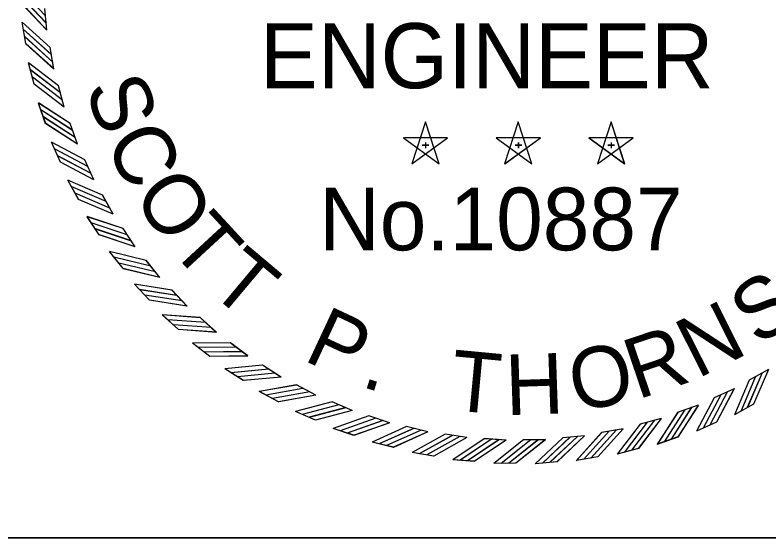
# Model space of a CAD drawing. Extents: x 0 to 1228740, y 0 to 152440.
# Drawn here: x 30.834 to 32.648, y 17.405 to 18.662 of the extents above; entities that cross this region are included whole.
import ezdxf

# ---------------------------------------------------------------- set-up
doc = ezdxf.new("R2010")
doc.units = 0
for name, color, linetype in [('R_No Plot', 7, 'Continuous'), ('R_Sheet Text', 7, 'Continuous'), ('STAMP', 7, 'Continuous')]:
    doc.layers.add(name, color=color, linetype=linetype)

msp = doc.modelspace()

# ---------------------------------------------------------------- linework, layer by layer
at = {"layer": 'R_No Plot'}
msp.add_lwpolyline([(30.6665, 20.1618), (33.4231, 20.1618), (33.4231, 17.4052), (30.6665, 17.4052)], close=True, dxfattribs=at)
msp.add_lwpolyline([(30.6665, 20.1432), (30.6665, 17.4052), (33.4231, 17.4052)], dxfattribs=at)
msp.add_lwpolyline([(30.6665, 20.1432), (30.6665, 17.4052), (33.4231, 17.4052)], dxfattribs=at)
at = {"layer": 'R_Sheet Text'}
for p, q in [((30.9105, 18.6254), (30.9057, 18.6779)), ((30.8599, 18.5933), (30.8508, 18.6451)), ((30.9275, 18.5323), (30.9184, 18.5842)), ((30.8798, 18.4961), (30.8664, 18.547)), ((30.9522, 18.4409), (30.9388, 18.4919)), ((30.9076, 18.4009), (30.89, 18.4505)), ((30.9843, 18.3519), (30.9667, 18.4016)), ((31.8214, 18.4051), (31.7885, 18.3041)), ((31.8542, 18.3042), (31.8215, 18.4053)), ((32.0446, 18.4051), (32.0117, 18.3041)), ((32.0774, 18.3042), (32.0447, 18.4053)), ((32.2678, 18.4051), (32.2349, 18.3041)), ((32.3006, 18.3042), (32.2679, 18.4053)), ((30.9432, 18.3083), (30.9216, 18.3563)), ((31.8745, 18.3666), (31.7682, 18.3667)), ((31.7683, 18.3666), (31.8542, 18.3041)), ((31.7886, 18.3042), (31.8746, 18.3666)), ((31.8215, 18.3553), (31.8215, 18.342)), ((32.0977, 18.3666), (31.9914, 18.3667)), ((31.9915, 18.3666), (32.0774, 18.3041)), ((32.0118, 18.3042), (32.0978, 18.3666)), ((32.0447, 18.3553), (32.0447, 18.342)), ((32.3209, 18.3666), (32.2147, 18.3667)), ((32.2147, 18.3666), (32.3006, 18.3041)), ((32.235, 18.3042), (32.321, 18.3666)), ((32.2679, 18.3553), (32.2679, 18.342)), ((31.8138, 18.3496), (31.8296, 18.3496)), ((32.037, 18.3496), (32.0528, 18.3496)), ((32.2603, 18.3496), (32.276, 18.3496)), ((31.0237, 18.2658), (31.0021, 18.3139)), ((30.9863, 18.219), (30.9608, 18.265)), ((31.07, 18.1832), (31.0445, 18.2294)), ((31.0366, 18.1335), (31.0074, 18.1773)), ((31.1231, 18.1048), (31.0938, 18.1487)), ((31.0939, 18.0525), (31.0612, 18.0937)), ((31.1824, 18.031), (31.1496, 18.0723)), ((31.1576, 17.9764), (31.1216, 18.0148)), ((31.2475, 17.9624), (31.2115, 18.0008)), ((31.2274, 17.9059), (31.1883, 17.9412)), ((31.3182, 17.8993), (31.279, 17.9347)), ((31.3027, 17.8415), (31.2609, 17.8734)), ((31.3938, 17.8424), (31.3519, 17.8744)), ((31.3832, 17.7834), (31.3388, 17.8118)), ((31.4738, 17.7918), (31.4294, 17.8203)), ((32.6463, 17.8101), (32.6001, 17.7846)), ((31.4681, 17.7322), (31.4216, 17.7568)), ((31.5578, 17.7481), (31.5112, 17.7728)), ((32.5637, 17.7638), (32.5156, 17.7421)), ((31.645, 17.7114), (31.5966, 17.7322)), ((32.4776, 17.7244), (32.4279, 17.7068)), ((32.6105, 17.7264), (32.5645, 17.7009)), ((31.557, 17.6882), (31.5086, 17.7089)), ((31.7351, 17.6821), (31.685, 17.6987)), ((32.3886, 17.6923), (32.3376, 17.6789)), ((31.6492, 17.6516), (31.5993, 17.6683)), ((31.8272, 17.6603), (31.7759, 17.6728)), ((32.2972, 17.6676), (32.2453, 17.6584)), ((32.5212, 17.6833), (32.4732, 17.6617)), ((31.9208, 17.6462), (31.8687, 17.6544)), ((32.2041, 17.6506), (32.1516, 17.6457)), ((32.4286, 17.6477), (32.379, 17.6301)), ((31.7442, 17.6229), (31.693, 17.6353)), ((32.0152, 17.6398), (31.9626, 17.6437)), ((32.1099, 17.6413), (32.0571, 17.6408)), ((32.3334, 17.6198), (32.2825, 17.6065)), ((31.8411, 17.602), (31.7891, 17.6102)), ((31.9395, 17.5892), (31.887, 17.5931)), ((32.2362, 17.6), (32.1844, 17.5909)), ((32.0386, 17.5846), (31.986, 17.5841)), ((32.1377, 17.5882), (32.0853, 17.5834))]:
    msp.add_line(p, q, dxfattribs=at)
for points in [[(30.9071, 18.6604), (30.8447, 18.7268)], [(30.9091, 18.6422), (30.8468, 18.7086)], [(30.9105, 18.6254), (30.8482, 18.6917)], [(30.9183, 18.5842), (30.8507, 18.6452)], [(30.9212, 18.5669), (30.8536, 18.6279)], [(30.9248, 18.5489), (30.8572, 18.6099)], [(30.9276, 18.5322), (30.86, 18.5932)], [(30.9388, 18.4918), (30.8663, 18.547)], [(30.9431, 18.4748), (30.8706, 18.53)], [(30.9481, 18.4573), (30.8757, 18.5125)], [(30.9523, 18.4409), (30.8798, 18.496)], [(30.9667, 18.4015), (30.89, 18.4505)], [(30.9724, 18.3849), (30.8957, 18.434)], [(30.9789, 18.3678), (30.9022, 18.4169)], [(30.9844, 18.3518), (30.9077, 18.4008)], [(31.0021, 18.3138), (30.9215, 18.3563)], [(31.0091, 18.2977), (30.9286, 18.3403)], [(31.017, 18.2812), (30.9364, 18.3238)], [(31.0238, 18.2657), (30.9433, 18.3082)], [(31.0445, 18.2293), (30.9608, 18.265)], [(31.0529, 18.2139), (30.9691, 18.2496)], [(31.0621, 18.1981), (30.9783, 18.2338)], [(31.0701, 18.1832), (30.9864, 18.2189)], [(31.0938, 18.1486), (31.0074, 18.1773)], [(31.1034, 18.1339), (31.017, 18.1626)], [(31.1139, 18.1189), (31.0274, 18.1476)], [(31.1231, 18.1048), (31.0367, 18.1335)], [(31.1496, 18.0723), (31.0611, 18.0937)], [(31.1604, 18.0584), (31.0719, 18.0799)], [(31.172, 18.0444), (31.0835, 18.0658)], [(31.1824, 18.031), (31.0939, 18.0524)], [(31.2115, 18.0008), (31.1215, 18.0148)], [(31.2234, 17.9879), (31.1334, 18.0019)], [(31.2362, 17.9748), (31.1462, 17.9889)], [(31.2476, 17.9624), (31.1577, 17.9764)], [(31.2791, 17.9346), (31.1883, 17.9412)], [(31.292, 17.9228), (31.2012, 17.9294)], [(31.3058, 17.9108), (31.215, 17.9174)], [(31.3183, 17.8993), (31.2274, 17.9059)], [(31.3519, 17.8743), (31.2608, 17.8734)], [(31.3657, 17.8636), (31.2747, 17.8626)], [(31.3805, 17.8528), (31.2894, 17.8519)], [(31.3939, 17.8424), (31.3028, 17.8414)], [(31.4294, 17.8202), (31.3388, 17.8118)], [(31.4441, 17.8106), (31.3535, 17.8022)], [(31.4597, 17.8011), (31.3691, 17.7927)], [(32.6156, 17.7929), (32.5799, 17.7092)], [(32.6314, 17.8021), (32.5957, 17.7184)], [(32.6463, 17.8102), (32.6106, 17.7264)], [(31.4739, 17.7918), (31.3832, 17.7834)], [(32.6002, 17.7846), (32.5645, 17.7008)], [(31.5112, 17.7727), (31.4215, 17.7568)], [(31.5266, 17.7644), (31.437, 17.7485)], [(31.543, 17.7562), (31.4533, 17.7403)], [(32.5483, 17.757), (32.5057, 17.6765)], [(32.5638, 17.7638), (32.5212, 17.6833)], [(31.5579, 17.7481), (31.4682, 17.7322)], [(32.5157, 17.7421), (32.4732, 17.6616)], [(32.5318, 17.7492), (32.4892, 17.6687)], [(31.5966, 17.7321), (31.5086, 17.7089)], [(31.6127, 17.7251), (31.5246, 17.7018)], [(32.4777, 17.7245), (32.4287, 17.6477)], [(31.6296, 17.7182), (31.5416, 17.695)], [(31.6451, 17.7114), (31.5571, 17.6882)], [(32.428, 17.7068), (32.379, 17.6301)], [(32.4446, 17.7125), (32.3955, 17.6358)], [(32.4617, 17.719), (32.4126, 17.6422)], [(31.6851, 17.6987), (31.5992, 17.6683)], [(31.7016, 17.693), (31.6158, 17.6626)], [(31.7191, 17.6876), (31.6333, 17.6572)], [(32.3722, 17.6882), (32.317, 17.6158)], [(32.3886, 17.6923), (32.3335, 17.6199)], [(31.7351, 17.6821), (31.6493, 17.6517)], [(31.776, 17.6727), (31.693, 17.6353)], [(31.793, 17.6684), (31.71, 17.631)], [(32.2973, 17.6677), (32.2363, 17.6001)], [(32.3377, 17.6788), (32.2825, 17.6064)], [(32.3547, 17.6831), (32.2995, 17.6107)], [(31.8108, 17.6645), (31.7278, 17.627)], [(31.8272, 17.6603), (31.7442, 17.6229)], [(31.8687, 17.6543), (31.7891, 17.6102)], [(31.886, 17.6514), (31.8064, 17.6073)], [(31.9041, 17.649), (31.8245, 17.6048)], [(32.1691, 17.6471), (32.1027, 17.5848)], [(32.1873, 17.6492), (32.1209, 17.5869)], [(32.2041, 17.6506), (32.1378, 17.5883)], [(32.2453, 17.6584), (32.1843, 17.5908)], [(32.2626, 17.6613), (32.2016, 17.5937)], [(32.2806, 17.6649), (32.2196, 17.5973)], [(31.9208, 17.6462), (31.8412, 17.602)], [(31.9627, 17.6436), (31.887, 17.5931)], [(31.9802, 17.6422), (31.9044, 17.5916)], [(31.9984, 17.6413), (31.9227, 17.5907)], [(32.0153, 17.6399), (31.9396, 17.5893)], [(32.0572, 17.6408), (31.9859, 17.5841)], [(32.0747, 17.6408), (32.0034, 17.5841)], [(32.093, 17.6413), (32.0217, 17.5847)], [(32.1099, 17.6413), (32.0387, 17.5847)], [(32.1516, 17.6457), (32.0853, 17.5834)]]:
    msp.add_lwpolyline(points, dxfattribs=at)
at = {"layer": 'STAMP'}
for p, q in [((30.9106, 18.6256), (30.9058, 18.6781)), ((30.86, 18.5934), (30.8509, 18.6453)), ((30.9276, 18.5324), (30.9185, 18.5844)), ((30.8799, 18.4962), (30.8665, 18.5471)), ((30.9523, 18.441), (30.9389, 18.492)), ((30.9077, 18.401), (30.8902, 18.4506)), ((30.9844, 18.352), (30.9669, 18.4017)), ((31.8215, 18.4053), (31.7886, 18.3043)), ((31.8543, 18.3043), (31.8216, 18.4054)), ((32.0448, 18.4053), (32.0118, 18.3043)), ((32.0776, 18.3043), (32.0448, 18.4054)), ((32.268, 18.4053), (32.2351, 18.3043)), ((32.3008, 18.3043), (32.2681, 18.4054)), ((30.9433, 18.3084), (30.9217, 18.3564)), ((31.8746, 18.3667), (31.7684, 18.3668)), ((31.7685, 18.3667), (31.8544, 18.3042)), ((31.7887, 18.3043), (31.8748, 18.3667)), ((31.8216, 18.3554), (31.8216, 18.3421)), ((32.0978, 18.3667), (31.9916, 18.3668)), ((31.9917, 18.3667), (32.0776, 18.3042)), ((32.012, 18.3043), (32.098, 18.3667)), ((32.0449, 18.3554), (32.0449, 18.3421)), ((32.3211, 18.3667), (32.2148, 18.3668)), ((32.2149, 18.3667), (32.3008, 18.3042)), ((32.2352, 18.3043), (32.3212, 18.3667)), ((32.2681, 18.3554), (32.2681, 18.3421)), ((31.814, 18.3497), (31.8298, 18.3497)), ((32.0372, 18.3497), (32.053, 18.3497)), ((32.2604, 18.3497), (32.2762, 18.3497)), ((31.0238, 18.2659), (31.0022, 18.314)), ((30.9864, 18.2191), (30.9609, 18.2651)), ((31.0702, 18.1834), (31.0446, 18.2295)), ((31.0367, 18.1336), (31.0076, 18.1774)), ((31.1232, 18.1049), (31.0939, 18.1488)), ((31.094, 18.0526), (31.0613, 18.0938)), ((31.1825, 18.0311), (31.1497, 18.0725)), ((31.1577, 17.9766), (31.1217, 18.015)), ((31.2477, 17.9625), (31.2116, 18.001)), ((31.2275, 17.9061), (31.1884, 17.9413)), ((31.3183, 17.8995), (31.2792, 17.9348)), ((31.3029, 17.8416), (31.261, 17.8735)), ((31.3939, 17.8425), (31.352, 17.8745)), ((31.3833, 17.7835), (31.339, 17.8119)), ((31.474, 17.792), (31.4295, 17.8204)), ((32.6465, 17.8102), (32.6003, 17.7847)), ((31.4682, 17.7323), (31.4217, 17.7569)), ((31.5579, 17.7482), (31.5113, 17.7729)), ((32.5639, 17.7639), (32.5158, 17.7423)), ((31.6452, 17.7115), (31.5967, 17.7323)), ((32.4778, 17.7245), (32.4281, 17.7069)), ((32.6107, 17.7265), (32.5647, 17.701)), ((31.5571, 17.6883), (31.5088, 17.709)), ((31.7352, 17.6822), (31.6852, 17.6989)), ((32.3888, 17.6924), (32.3378, 17.679)), ((32.5214, 17.6834), (32.4734, 17.6618)), ((31.6494, 17.6518), (31.5994, 17.6684)), ((31.8273, 17.6604), (31.7761, 17.6729)), ((32.2974, 17.6677), (32.2454, 17.6586)), ((31.9209, 17.6463), (31.8688, 17.6545)), ((32.2042, 17.6507), (32.1517, 17.6458)), ((32.4288, 17.6478), (32.3792, 17.6302)), ((31.7443, 17.623), (31.6932, 17.6354)), ((32.0154, 17.6399), (31.9628, 17.6438)), ((32.11, 17.6414), (32.0573, 17.6409)), ((32.3336, 17.62), (32.2827, 17.6066)), ((31.8413, 17.6021), (31.7893, 17.6103)), ((31.9397, 17.5893), (31.8872, 17.5932)), ((32.2364, 17.6001), (32.1845, 17.591)), ((32.0387, 17.5847), (31.9861, 17.5842)), ((32.1379, 17.5883), (32.0855, 17.5835))]:
    msp.add_line(p, q, dxfattribs=at)
for points in [[(30.9072, 18.6605), (30.8448, 18.7269)], [(30.9093, 18.6424), (30.8469, 18.7087)], [(30.9107, 18.6255), (30.8483, 18.6919)], [(30.9185, 18.5843), (30.8508, 18.6453)], [(30.9213, 18.567), (30.8537, 18.628)], [(30.9249, 18.5491), (30.8573, 18.6101)], [(30.9277, 18.5324), (30.8601, 18.5934)], [(30.9389, 18.492), (30.8664, 18.5472)], [(30.9432, 18.475), (30.8708, 18.5302)], [(30.9482, 18.4574), (30.8758, 18.5126)], [(30.9524, 18.441), (30.8799, 18.4962)], [(30.9668, 18.4016), (30.8901, 18.4507)], [(30.9725, 18.3851), (30.8958, 18.4341)], [(30.979, 18.368), (30.9023, 18.417)], [(30.9845, 18.3519), (30.9078, 18.401)], [(31.0022, 18.3139), (30.9217, 18.3565)], [(31.0092, 18.2979), (30.9287, 18.3404)], [(31.0171, 18.2814), (30.9366, 18.3239)], [(31.0239, 18.2659), (30.9434, 18.3084)], [(31.0446, 18.2294), (30.9609, 18.2652)], [(31.053, 18.214), (30.9692, 18.2497)], [(31.0622, 18.1982), (30.9784, 18.2339)], [(31.0702, 18.1833), (30.9865, 18.219)], [(31.0939, 18.1487), (31.0075, 18.1774)], [(31.1035, 18.1341), (31.0171, 18.1627)], [(31.114, 18.1191), (31.0276, 18.1478)], [(31.1232, 18.1049), (31.0368, 18.1336)], [(31.1497, 18.0724), (31.0612, 18.0938)], [(31.1605, 18.0585), (31.072, 18.08)], [(31.1721, 18.0445), (31.0837, 18.0659)], [(31.1826, 18.0311), (31.0941, 18.0526)], [(31.2116, 18.0009), (31.1216, 18.015)], [(31.2235, 17.988), (31.1335, 18.0021)], [(31.2363, 17.9749), (31.1463, 17.989)], [(31.2477, 17.9625), (31.1578, 17.9765)], [(31.2792, 17.9348), (31.1884, 17.9414)], [(31.2921, 17.9229), (31.2013, 17.9295)], [(31.3059, 17.9109), (31.2151, 17.9175)], [(31.3184, 17.8995), (31.2276, 17.9061)], [(31.352, 17.8744), (31.261, 17.8735)], [(31.3659, 17.8637), (31.2748, 17.8627)], [(31.3806, 17.8529), (31.2896, 17.852)], [(31.394, 17.8425), (31.3029, 17.8416)], [(31.4296, 17.8203), (31.3389, 17.8119)], [(31.4442, 17.8107), (31.3536, 17.8023)], [(32.6465, 17.8103), (32.6108, 17.7266)], [(31.4599, 17.8012), (31.3692, 17.7928)], [(32.6158, 17.793), (32.5801, 17.7093)], [(32.6316, 17.8022), (32.5959, 17.7185)], [(31.474, 17.792), (31.3834, 17.7835)], [(32.6004, 17.7847), (32.5646, 17.7009)], [(31.5113, 17.7728), (31.4217, 17.7569)], [(31.5267, 17.7645), (31.4371, 17.7486)], [(31.5431, 17.7563), (31.4534, 17.7404)], [(32.5484, 17.7572), (32.5059, 17.6766)], [(32.5639, 17.764), (32.5214, 17.6834)], [(31.558, 17.7482), (31.4683, 17.7323)], [(32.5159, 17.7422), (32.4734, 17.6617)], [(32.5319, 17.7493), (32.4894, 17.6688)], [(31.5967, 17.7322), (31.5087, 17.709)], [(31.6128, 17.7252), (31.5248, 17.7019)], [(32.4779, 17.7246), (32.4288, 17.6478)], [(31.6298, 17.7184), (31.5417, 17.6951)], [(31.6453, 17.7115), (31.5572, 17.6883)], [(32.4282, 17.7069), (32.3791, 17.6302)], [(32.4447, 17.7126), (32.3957, 17.6359)], [(32.4618, 17.7191), (32.4128, 17.6423)], [(31.6852, 17.6988), (31.5994, 17.6684)], [(31.7018, 17.6931), (31.616, 17.6627)], [(31.7193, 17.6877), (31.6334, 17.6573)], [(32.3724, 17.6883), (32.3172, 17.6159)], [(32.3888, 17.6924), (32.3336, 17.62)], [(31.7353, 17.6822), (31.6495, 17.6518)], [(31.7761, 17.6728), (31.6931, 17.6354)], [(31.7931, 17.6685), (31.7101, 17.6311)], [(32.2974, 17.6678), (32.2364, 17.6002)], [(32.3378, 17.6789), (32.2826, 17.6065)], [(32.3548, 17.6832), (32.2996, 17.6108)], [(31.811, 17.6646), (31.728, 17.6271)], [(31.8274, 17.6604), (31.7444, 17.623)], [(31.8689, 17.6544), (31.7892, 17.6103)], [(31.8862, 17.6515), (31.8065, 17.6074)], [(31.9043, 17.6491), (31.8247, 17.6049)], [(32.1693, 17.6473), (32.1029, 17.5849)], [(32.1874, 17.6493), (32.1211, 17.587)], [(32.2043, 17.6507), (32.1379, 17.5884)], [(32.2455, 17.6585), (32.1845, 17.5909)], [(32.2628, 17.6614), (32.2018, 17.5938)], [(32.2807, 17.665), (32.2197, 17.5974)], [(31.921, 17.6463), (31.8414, 17.6021)], [(31.9628, 17.6437), (31.8871, 17.5932)], [(31.9803, 17.6423), (31.9046, 17.5917)], [(31.9986, 17.6414), (31.9228, 17.5908)], [(32.0154, 17.64), (31.9397, 17.5894)], [(32.0574, 17.6409), (31.9861, 17.5842)], [(32.0749, 17.6409), (32.0036, 17.5842)], [(32.0932, 17.6414), (32.0219, 17.5848)], [(32.1101, 17.6414), (32.0388, 17.5848)], [(32.1518, 17.6458), (32.0854, 17.5835)]]:
    msp.add_lwpolyline(points, dxfattribs=at)

# ---------------------------------------------------------------- texts
at = {"layer": 'R_Sheet Text'}
for s, height, p in [('ENGINEER', 0.15625, (31.4231, 18.4861)), ('No.10887', 0.15067, (31.5659, 18.0965))]:
    msp.add_text(s, height=height, dxfattribs=at).set_placement(p)
for s, rotation, p in [('S', 289.7007, (31.001, 18.4878)), ('C', 296.9967, (31.0477, 18.3572)), ('O', 304.6575, (31.1143, 18.2277)), ('T', 312.6831, (31.2018, 18.1029)), ('T', 319.9791, (31.2958, 18.0009)), ('S', 35.4928, (32.6231, 17.8636)), ('P', 334.9359, (31.5247, 17.8335)), ('N', 26.7376, (32.4755, 17.7869)), ('R', 18.712, (32.3314, 17.737)), ('O', 10.6864, (32.1817, 17.7078)), ('T', 354.6351, (31.8775, 17.713)), ('H', 1.9312, (32.0156, 17.7)), ('.', 342.9615, (31.6633, 17.7698))]:
    msp.add_text(s, height=0.1454, rotation=rotation, dxfattribs=at).set_placement(p)
at = {"layer": 'STAMP'}
for s, height, p in [('ENGINEER', 0.15625, (31.4232, 18.4862)), ('No.10887', 0.15067, (31.5661, 18.0966))]:
    msp.add_text(s, height=height, dxfattribs=at).set_placement(p)
for s, rotation, p in [('S', 289.7007, (31.0011, 18.4879)), ('C', 296.9967, (31.0479, 18.3574)), ('O', 304.6575, (31.1144, 18.2279)), ('T', 312.6831, (31.2019, 18.103)), ('T', 319.9791, (31.2959, 18.0011)), ('S', 35.4928, (32.6233, 17.8637)), ('P', 334.9359, (31.5249, 17.8336)), ('N', 26.7376, (32.4757, 17.787)), ('R', 18.712, (32.3316, 17.7371)), ('O', 10.6864, (32.1819, 17.7079)), ('T', 354.6351, (31.8777, 17.7131)), ('H', 1.9312, (32.0157, 17.7001)), ('.', 342.9615, (31.6634, 17.7699))]:
    msp.add_text(s, height=0.1454, rotation=rotation, dxfattribs=at).set_placement(p)

doc.saveas('drawing.dxf')
